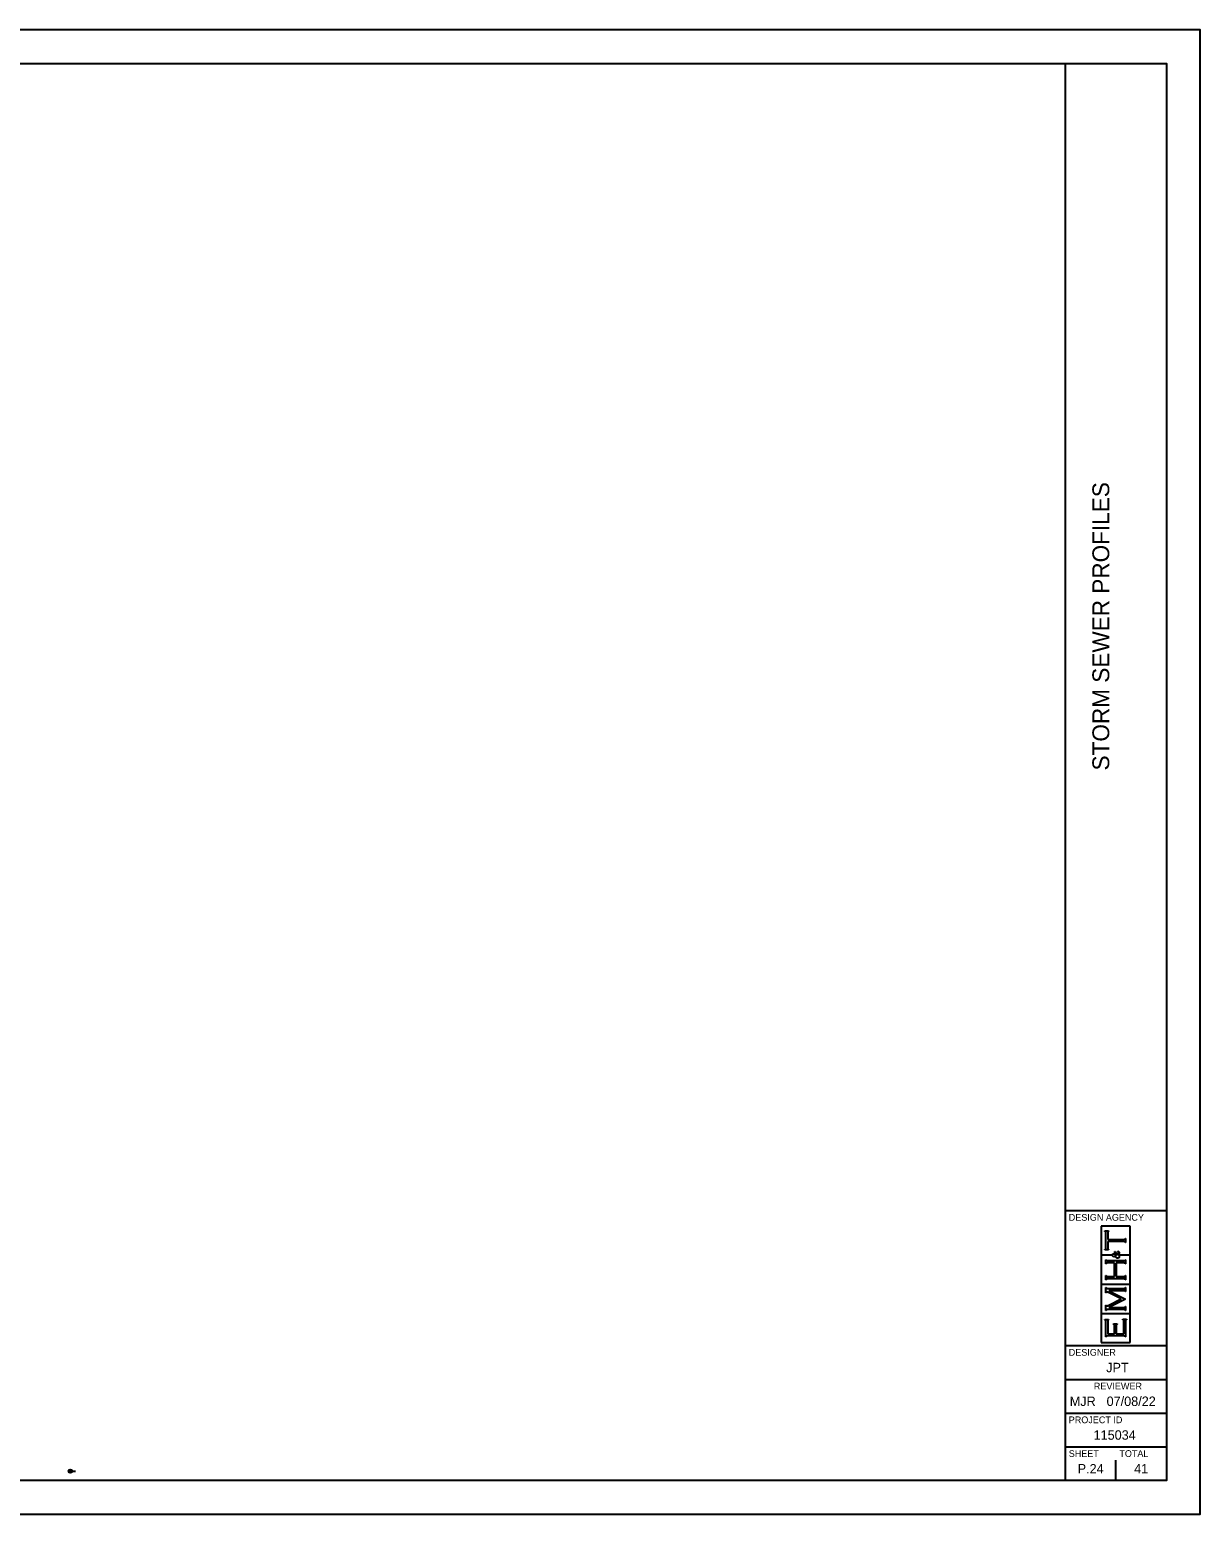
# Model space of a CAD drawing. Extents: x -0.7 to 34, y 0 to 22.
# Drawn here: x 16.65 to 34, y 0 to 22 of the extents above; entities that cross this region are included whole.
import ezdxf

# ---------------------------------------------------------------- set-up
doc = ezdxf.new("R2010")
doc.units = 0
for name, color, linetype in [('SH_Border', 7, 'Continuous'), ('SH_Cut_Line', 7, 'Continuous'), ('SH_Data', 7, 'Continuous'), ('SH_Named_Boundary', 7, 'Continuous')]:
    doc.layers.add(name, color=color, linetype=linetype)

msp = doc.modelspace()

# ---------------------------------------------------------------- linework, layer by layer
at = {"layer": 'SH_Border'}
for p, q in [((32, 0.5), (32, 21.5)), ((32, 4.5), (33.5, 4.5)), ((32, 2.5), (33.5, 2.5)), ((32, 2), (33.5, 2)), ((32, 1.5), (33.5, 1.5)), ((32, 1), (33.5, 1))]:
    msp.add_line(p, q, dxfattribs=at)
msp.add_lwpolyline([(1.5, 21.5), (33.5, 21.5), (33.5, 0.5), (1.5, 0.5)], close=True, dxfattribs=at)
at = {"layer": 'SH_Cut_Line'}
msp.add_lwpolyline([(0, 0), (34, 0), (34, 22), (0, 22)], close=True, dxfattribs=at)
at = {"layer": 'SH_Data'}
for p, q in [((32.959, 4.271), (32.532, 4.271)), ((32.532, 4.271), (32.532, 3.844)), ((32.585, 4.192), (32.585, 4.199)), ((32.585, 4.199), (32.641, 4.199)), ((32.591, 4.191), (32.585, 4.192)), ((32.595, 4.189), (32.591, 4.191)), ((32.596, 4.186), (32.595, 4.189)), ((32.598, 4.184), (32.596, 4.186)), ((32.599, 4.179), (32.598, 4.184)), ((32.628, 4.184), (32.627, 4.179)), ((32.63, 4.186), (32.628, 4.184)), ((32.632, 4.189), (32.63, 4.186)), ((32.636, 4.191), (32.632, 4.189)), ((32.641, 4.192), (32.636, 4.191)), ((32.641, 4.199), (32.641, 4.192)), ((32.959, 3.844), (32.959, 4.271)), ((32.599, 4.173), (32.599, 4.179)), ((32.599, 3.942), (32.599, 4.173)), ((32.627, 4.179), (32.627, 4.173)), ((32.627, 4.173), (32.627, 4.074)), ((32.627, 4.074), (32.867, 4.074)), ((32.867, 4.041), (32.627, 4.041)), ((32.627, 4.041), (32.627, 3.942)), ((32.867, 4.074), (32.872, 4.074)), ((32.873, 4.041), (32.867, 4.041)), ((32.872, 4.074), (32.877, 4.075)), ((32.877, 4.04), (32.873, 4.041)), ((32.877, 4.075), (32.879, 4.077)), ((32.879, 4.038), (32.877, 4.04)), ((32.879, 4.077), (32.882, 4.079)), ((32.882, 4.036), (32.879, 4.038)), ((32.882, 4.079), (32.884, 4.083)), ((32.884, 4.033), (32.882, 4.036)), ((32.884, 4.083), (32.885, 4.088)), ((32.885, 4.027), (32.884, 4.033)), ((32.885, 4.088), (32.892, 4.088)), ((32.892, 4.027), (32.885, 4.027)), ((32.892, 4.088), (32.892, 4.027)), ((32.532, 3.844), (32.689, 3.844)), ((32.689, 3.838), (32.532, 3.838)), ((32.532, 3.838), (32.532, 3.411)), ((32.585, 3.923), (32.591, 3.925)), ((32.585, 3.917), (32.585, 3.923)), ((32.641, 3.917), (32.585, 3.917)), ((32.591, 3.925), (32.595, 3.927)), ((32.595, 3.927), (32.596, 3.929)), ((32.596, 3.929), (32.598, 3.932)), ((32.598, 3.932), (32.599, 3.936)), ((32.599, 3.936), (32.599, 3.942)), ((32.599, 3.711), (32.599, 3.772)), ((32.599, 3.772), (32.606, 3.772)), ((32.606, 3.772), (32.607, 3.767)), ((32.607, 3.767), (32.609, 3.763)), ((32.609, 3.763), (32.612, 3.761)), ((32.612, 3.761), (32.614, 3.759)), ((32.614, 3.759), (32.618, 3.759)), ((32.618, 3.759), (32.624, 3.759)), ((32.624, 3.759), (32.867, 3.759)), ((32.627, 3.942), (32.627, 3.936)), ((32.627, 3.936), (32.628, 3.932)), ((32.628, 3.932), (32.63, 3.929)), ((32.63, 3.929), (32.632, 3.927)), ((32.632, 3.927), (32.636, 3.925)), ((32.636, 3.925), (32.641, 3.923)), ((32.641, 3.923), (32.641, 3.917)), ((32.689, 3.844), (32.689, 3.838)), ((32.697, 3.848), (32.699, 3.853)), ((32.697, 3.842), (32.697, 3.848)), ((32.697, 3.836), (32.697, 3.842)), ((32.699, 3.831), (32.697, 3.836)), ((32.699, 3.853), (32.702, 3.856)), ((32.702, 3.826), (32.699, 3.831)), ((32.702, 3.856), (32.705, 3.86)), ((32.706, 3.82), (32.702, 3.826)), ((32.705, 3.86), (32.71, 3.862)), ((32.713, 3.817), (32.706, 3.82)), ((32.71, 3.862), (32.714, 3.862)), ((32.721, 3.817), (32.713, 3.817)), ((32.714, 3.862), (32.72, 3.862)), ((32.72, 3.862), (32.724, 3.86)), ((32.724, 3.817), (32.721, 3.817)), ((32.724, 3.86), (32.728, 3.856)), ((32.727, 3.818), (32.724, 3.817)), ((32.73, 3.819), (32.727, 3.818)), ((32.728, 3.856), (32.732, 3.853)), ((32.733, 3.819), (32.73, 3.819)), ((32.732, 3.853), (32.736, 3.847)), ((32.737, 3.821), (32.733, 3.819)), ((32.734, 3.863), (32.734, 3.893)), ((32.734, 3.893), (32.737, 3.893)), ((32.737, 3.863), (32.734, 3.863)), ((32.736, 3.847), (32.74, 3.838)), ((32.737, 3.893), (32.737, 3.889)), ((32.737, 3.889), (32.738, 3.886)), ((32.738, 3.867), (32.737, 3.865)), ((32.737, 3.865), (32.737, 3.863)), ((32.742, 3.823), (32.737, 3.821)), ((32.738, 3.886), (32.739, 3.884)), ((32.739, 3.868), (32.738, 3.867)), ((32.739, 3.884), (32.741, 3.882)), ((32.741, 3.869), (32.739, 3.868)), ((32.74, 3.838), (32.751, 3.844)), ((32.741, 3.882), (32.745, 3.879)), ((32.742, 3.87), (32.741, 3.869)), ((32.745, 3.87), (32.742, 3.87)), ((32.748, 3.812), (32.742, 3.823)), ((32.745, 3.879), (32.753, 3.875)), ((32.751, 3.87), (32.745, 3.87)), ((32.754, 3.804), (32.748, 3.812)), ((32.76, 3.866), (32.751, 3.87)), ((32.751, 3.844), (32.761, 3.851)), ((32.753, 3.875), (32.76, 3.871)), ((32.76, 3.8), (32.754, 3.804)), ((32.76, 3.871), (32.767, 3.866)), ((32.77, 3.857), (32.76, 3.866)), ((32.766, 3.796), (32.76, 3.8)), ((32.761, 3.851), (32.77, 3.857)), ((32.771, 3.794), (32.766, 3.796)), ((32.767, 3.866), (32.774, 3.861)), ((32.777, 3.794), (32.771, 3.794)), ((32.774, 3.861), (32.779, 3.865)), ((32.777, 3.895), (32.779, 3.898)), ((32.78, 3.894), (32.777, 3.895)), ((32.783, 3.794), (32.777, 3.794)), ((32.779, 3.898), (32.785, 3.896)), ((32.779, 3.865), (32.782, 3.869)), ((32.783, 3.892), (32.78, 3.894)), ((32.782, 3.869), (32.784, 3.872)), ((32.785, 3.89), (32.783, 3.892)), ((32.788, 3.796), (32.783, 3.794)), ((32.784, 3.872), (32.786, 3.875)), ((32.789, 3.855), (32.784, 3.851)), ((32.784, 3.851), (32.79, 3.845)), ((32.785, 3.896), (32.79, 3.893)), ((32.786, 3.888), (32.785, 3.89)), ((32.787, 3.885), (32.786, 3.888)), ((32.786, 3.875), (32.787, 3.879)), ((32.787, 3.882), (32.787, 3.885)), ((32.787, 3.879), (32.787, 3.882)), ((32.792, 3.801), (32.788, 3.796)), ((32.793, 3.86), (32.789, 3.855)), ((32.79, 3.893), (32.794, 3.889)), ((32.79, 3.845), (32.793, 3.839)), ((32.796, 3.805), (32.792, 3.801)), ((32.795, 3.864), (32.793, 3.86)), ((32.793, 3.839), (32.795, 3.835)), ((32.794, 3.889), (32.797, 3.885)), ((32.797, 3.868), (32.795, 3.864)), ((32.795, 3.835), (32.797, 3.83)), ((32.798, 3.811), (32.796, 3.805)), ((32.797, 3.885), (32.798, 3.881)), ((32.798, 3.872), (32.797, 3.868)), ((32.797, 3.83), (32.798, 3.825)), ((32.798, 3.881), (32.798, 3.876)), ((32.798, 3.876), (32.798, 3.872)), ((32.802, 3.838), (32.798, 3.844)), ((32.798, 3.844), (32.959, 3.844)), ((32.798, 3.825), (32.798, 3.819)), ((32.798, 3.819), (32.798, 3.811)), ((32.959, 3.838), (32.802, 3.838)), ((32.867, 3.759), (32.872, 3.759)), ((32.872, 3.759), (32.877, 3.759)), ((32.877, 3.759), (32.879, 3.761)), ((32.879, 3.761), (32.882, 3.763)), ((32.882, 3.763), (32.884, 3.767)), ((32.884, 3.767), (32.885, 3.772)), ((32.885, 3.772), (32.892, 3.772)), ((32.892, 3.772), (32.892, 3.711)), ((32.959, 3.411), (32.959, 3.838)), ((32.606, 3.711), (32.599, 3.711)), ((32.599, 3.476), (32.599, 3.537)), ((32.599, 3.537), (32.606, 3.537)), ((32.607, 3.717), (32.606, 3.711)), ((32.606, 3.537), (32.607, 3.532)), ((32.609, 3.72), (32.607, 3.717)), ((32.607, 3.532), (32.609, 3.528)), ((32.612, 3.722), (32.609, 3.72)), ((32.609, 3.528), (32.612, 3.527)), ((32.614, 3.724), (32.612, 3.722)), ((32.612, 3.527), (32.614, 3.525)), ((32.618, 3.725), (32.614, 3.724)), ((32.614, 3.525), (32.618, 3.524)), ((32.624, 3.725), (32.618, 3.725)), ((32.618, 3.524), (32.624, 3.524)), ((32.727, 3.725), (32.624, 3.725)), ((32.624, 3.524), (32.727, 3.524)), ((32.727, 3.524), (32.727, 3.725)), ((32.867, 3.725), (32.755, 3.725)), ((32.755, 3.725), (32.755, 3.524)), ((32.755, 3.524), (32.867, 3.524)), ((32.873, 3.725), (32.867, 3.725)), ((32.867, 3.524), (32.873, 3.524)), ((32.877, 3.724), (32.873, 3.725)), ((32.873, 3.524), (32.877, 3.525)), ((32.879, 3.722), (32.877, 3.724)), ((32.877, 3.525), (32.879, 3.526)), ((32.882, 3.72), (32.879, 3.722)), ((32.879, 3.526), (32.882, 3.528)), ((32.884, 3.717), (32.882, 3.72)), ((32.882, 3.528), (32.884, 3.532)), ((32.885, 3.711), (32.884, 3.717)), ((32.884, 3.532), (32.885, 3.537)), ((32.892, 3.711), (32.885, 3.711)), ((32.885, 3.537), (32.892, 3.537)), ((32.892, 3.537), (32.892, 3.476)), ((32.532, 3.411), (32.959, 3.411)), ((32.959, 3.405), (32.532, 3.405)), ((32.532, 3.405), (32.532, 2.977)), ((32.606, 3.476), (32.599, 3.476)), ((32.599, 3.284), (32.599, 3.361)), ((32.599, 3.361), (32.606, 3.361)), ((32.607, 3.482), (32.606, 3.476)), ((32.606, 3.361), (32.607, 3.355)), ((32.609, 3.486), (32.607, 3.482)), ((32.607, 3.355), (32.609, 3.352)), ((32.612, 3.487), (32.609, 3.486)), ((32.609, 3.352), (32.612, 3.35)), ((32.614, 3.489), (32.612, 3.487)), ((32.612, 3.35), (32.614, 3.348)), ((32.618, 3.49), (32.614, 3.489)), ((32.614, 3.348), (32.618, 3.347)), ((32.624, 3.49), (32.618, 3.49)), ((32.618, 3.347), (32.624, 3.347)), ((32.867, 3.49), (32.624, 3.49)), ((32.624, 3.347), (32.867, 3.347)), ((32.867, 3.314), (32.645, 3.314)), ((32.645, 3.314), (32.892, 3.189)), ((32.75, 3.5), (32.75, 3.5)), ((32.873, 3.49), (32.867, 3.49)), ((32.867, 3.347), (32.872, 3.347)), ((32.873, 3.314), (32.867, 3.314)), ((32.872, 3.347), (32.877, 3.348)), ((32.877, 3.489), (32.873, 3.49)), ((32.877, 3.313), (32.873, 3.314)), ((32.879, 3.488), (32.877, 3.489)), ((32.877, 3.348), (32.879, 3.35)), ((32.879, 3.311), (32.877, 3.313)), ((32.882, 3.486), (32.879, 3.488)), ((32.879, 3.35), (32.882, 3.352)), ((32.882, 3.309), (32.879, 3.311)), ((32.884, 3.482), (32.882, 3.486)), ((32.882, 3.352), (32.884, 3.355)), ((32.884, 3.305), (32.882, 3.309)), ((32.885, 3.476), (32.884, 3.482)), ((32.884, 3.355), (32.885, 3.361)), ((32.885, 3.3), (32.884, 3.305)), ((32.892, 3.476), (32.885, 3.476)), ((32.885, 3.361), (32.892, 3.361)), ((32.892, 3.361), (32.892, 3.3)), ((32.959, 2.977), (32.959, 3.405)), ((32.606, 3.284), (32.599, 3.284)), ((32.599, 3.022), (32.599, 3.097)), ((32.599, 3.097), (32.606, 3.097)), ((32.608, 3.291), (32.606, 3.284)), ((32.606, 3.097), (32.608, 3.09)), ((32.612, 3.295), (32.608, 3.291)), ((32.608, 3.09), (32.611, 3.087)), ((32.611, 3.087), (32.615, 3.087)), ((32.615, 3.295), (32.612, 3.295)), ((32.618, 3.295), (32.615, 3.295)), ((32.615, 3.087), (32.617, 3.087)), ((32.617, 3.087), (32.622, 3.089)), ((32.623, 3.293), (32.618, 3.295)), ((32.622, 3.089), (32.632, 3.094)), ((32.63, 3.29), (32.623, 3.293)), ((32.826, 3.192), (32.63, 3.29)), ((32.632, 3.094), (32.826, 3.192)), ((32.892, 3.189), (32.645, 3.066)), ((32.892, 3.3), (32.885, 3.3)), ((32.532, 2.977), (32.959, 2.977)), ((32.959, 2.972), (32.532, 2.972)), ((32.532, 2.972), (32.532, 2.544)), ((32.585, 2.88), (32.585, 2.887)), ((32.585, 2.887), (32.641, 2.887)), ((32.591, 2.878), (32.585, 2.88)), ((32.595, 2.877), (32.591, 2.878)), ((32.596, 2.874), (32.595, 2.877)), ((32.598, 2.872), (32.596, 2.874)), ((32.599, 2.867), (32.598, 2.872)), ((32.606, 3.022), (32.599, 3.022)), ((32.599, 2.861), (32.599, 2.867)), ((32.599, 2.629), (32.599, 2.861)), ((32.607, 3.027), (32.606, 3.022)), ((32.609, 3.031), (32.607, 3.027)), ((32.612, 3.032), (32.609, 3.031)), ((32.614, 3.034), (32.612, 3.032)), ((32.618, 3.035), (32.614, 3.034)), ((32.624, 3.035), (32.618, 3.035)), ((32.867, 3.035), (32.624, 3.035)), ((32.628, 2.872), (32.627, 2.867)), ((32.627, 2.867), (32.627, 2.861)), ((32.627, 2.861), (32.627, 2.676)), ((32.63, 2.874), (32.628, 2.872)), ((32.632, 2.877), (32.63, 2.874)), ((32.636, 2.879), (32.632, 2.877)), ((32.641, 2.88), (32.636, 2.879)), ((32.641, 2.887), (32.641, 2.88)), ((32.645, 3.066), (32.867, 3.066)), ((32.85, 2.883), (32.85, 2.89)), ((32.85, 2.89), (32.906, 2.89)), ((32.855, 2.882), (32.85, 2.883)), ((32.859, 2.88), (32.855, 2.882)), ((32.861, 2.877), (32.859, 2.88)), ((32.863, 2.875), (32.861, 2.877)), ((32.864, 2.87), (32.863, 2.875)), ((32.864, 2.864), (32.864, 2.87)), ((32.864, 2.676), (32.864, 2.864)), ((32.867, 3.066), (32.872, 3.066)), ((32.873, 3.035), (32.867, 3.035)), ((32.872, 3.066), (32.877, 3.067)), ((32.877, 3.034), (32.873, 3.035)), ((32.877, 3.067), (32.879, 3.069)), ((32.879, 3.032), (32.877, 3.034)), ((32.879, 3.069), (32.882, 3.07)), ((32.882, 3.031), (32.879, 3.032)), ((32.882, 3.07), (32.884, 3.074)), ((32.884, 3.027), (32.882, 3.031)), ((32.884, 3.074), (32.885, 3.079)), ((32.885, 3.022), (32.884, 3.027)), ((32.885, 3.079), (32.892, 3.079)), ((32.892, 3.022), (32.885, 3.022)), ((32.892, 3.079), (32.892, 3.022)), ((32.893, 2.875), (32.892, 2.87)), ((32.892, 2.87), (32.892, 2.864)), ((32.892, 2.864), (32.892, 2.629)), ((32.895, 2.877), (32.893, 2.875)), ((32.897, 2.88), (32.895, 2.877)), ((32.9, 2.882), (32.897, 2.88)), ((32.906, 2.883), (32.9, 2.882)), ((32.906, 2.89), (32.906, 2.883)), ((32.959, 2.544), (32.959, 2.972)), ((32.612, 2.64), (32.609, 2.638)), ((32.614, 2.642), (32.612, 2.64)), ((32.618, 2.643), (32.614, 2.642)), ((32.624, 2.643), (32.618, 2.643)), ((32.867, 2.643), (32.624, 2.643)), ((32.627, 2.676), (32.727, 2.676)), ((32.714, 2.816), (32.714, 2.823)), ((32.714, 2.823), (32.769, 2.823)), ((32.719, 2.815), (32.714, 2.816)), ((32.723, 2.813), (32.719, 2.815)), ((32.724, 2.81), (32.723, 2.813)), ((32.726, 2.808), (32.724, 2.81)), ((32.727, 2.803), (32.726, 2.808)), ((32.727, 2.797), (32.727, 2.803)), ((32.727, 2.676), (32.727, 2.797)), ((32.756, 2.808), (32.755, 2.803)), ((32.755, 2.803), (32.755, 2.797)), ((32.755, 2.797), (32.755, 2.676)), ((32.755, 2.676), (32.864, 2.676)), ((32.758, 2.81), (32.756, 2.808)), ((32.76, 2.813), (32.758, 2.81)), ((32.764, 2.815), (32.76, 2.813)), ((32.769, 2.816), (32.764, 2.815)), ((32.769, 2.823), (32.769, 2.816)), ((32.873, 2.643), (32.867, 2.643)), ((32.877, 2.642), (32.873, 2.643)), ((32.879, 2.64), (32.877, 2.642)), ((32.882, 2.638), (32.879, 2.64)), ((32.532, 2.544), (32.959, 2.544)), ((32.606, 2.629), (32.599, 2.629)), ((32.607, 2.635), (32.606, 2.629)), ((32.609, 2.638), (32.607, 2.635)), ((32.884, 2.635), (32.882, 2.638)), ((32.885, 2.629), (32.884, 2.635)), ((32.892, 2.629), (32.885, 2.629)), ((32.375, 0.675), (32.375, 0.675)), ((32.75, 0.5), (32.75, 0.8))]:
    msp.add_line(p, q, dxfattribs=at)
at = {"layer": 'SH_Named_Boundary'}
for p, q in [((17.224, 0.639), (17.276, 0.639)), ((17.25, 0.639), (17.328, 0.639))]:
    msp.add_line(p, q, dxfattribs=at)
msp.add_circle((17.25, 0.639), 0.026, dxfattribs=at)

# ---------------------------------------------------------------- texts
at = {"layer": 'SH_Data'}
msp.add_text('STORM SEWER PROFILES', height=0.25, rotation=90, dxfattribs=at).set_placement((32.65, 11.023))
for s, height, p in [('DESIGN AGENCY', 0.1, (32.05, 4.35)), ('DESIGNER', 0.1, (32.05, 2.35)), ('JPT', 0.14, (32.605, 2.105)), ('REVIEWER', 0.1, (32.422, 1.85)), ('MJR', 0.14, (32.065, 1.605)), ('07/08/22', 0.14, (32.611, 1.605)), ('PROJECT ID', 0.1, (32.05, 1.35)), ('115034', 0.14, (32.418, 1.105)), ('SHEET', 0.1, (32.05, 0.85)), ('TOTAL', 0.1, (32.8, 0.85)), ('P.24', 0.14, (32.182, 0.605)), ('41', 0.14, (33.019, 0.605))]:
    msp.add_text(s, height=height, dxfattribs=at).set_placement(p)
at = {"layer": 'SH_Named_Boundary'}
for s, p in [('P.22', (17.245, 0.629)), ('3', (17.249, 0.645)), ('Profile Run1 - EX2-D2', (17.282, 0.645)), ('1:10', (17.282, 0.629))]:
    msp.add_text(s, height=0.00328, dxfattribs=at).set_placement(p)

doc.saveas('drawing.dxf')
